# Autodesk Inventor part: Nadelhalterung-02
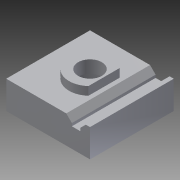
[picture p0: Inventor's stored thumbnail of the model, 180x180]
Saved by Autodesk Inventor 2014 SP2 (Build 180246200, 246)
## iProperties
Company: VDW-Nachwuchsstiftung
Created: 2014-04
Part Number: Nadelhalterung-02
Project: Verstellbarer Werkstückanschlag
Material: Aluminium 6061
Document SubType Name: Modeling
Designer: e_dammj
Density: 2.71 g/cm^3
Appearance: Aluminium - flach
Mass: 20.6232 g
Surface Area: 35.8794 cm^2
Volume: 7.61003 cm^3
Author: e_dammj
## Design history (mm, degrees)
derived "DesignModel.ipt"
feature "Volumenkörper1::DesignModel.ipt"
tag "Bezeichnung1"
node "Volumenkörper1"
other parameters: "d3" = 0, "d4" = 15, "d5" = 3, "d6" = 0, "d7" = 8.5, "d9" = 13.5, "d10" = 8.5, "d15" = 3, "d17" = 1, "d18" = 3, "d19" = 45 deg, "d21" = 0, "d23" = 0, "d24" = 12.5
